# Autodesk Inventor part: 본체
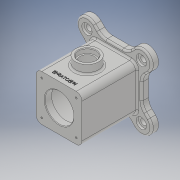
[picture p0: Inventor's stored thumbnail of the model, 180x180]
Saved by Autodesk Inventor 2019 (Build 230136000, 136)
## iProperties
Created: 2021-01
Part Number: 본체
Material: 일반
Document SubType Name: Modeling
Designer: 3dpro14
Density: 1 g/cm^3
Appearance: 기본값
Mass: 385.865 g
Surface Area: 854.376 cm^2
Volume: 385.865 cm^3
Author: 3dpro14
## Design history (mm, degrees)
sketch "스케치1" dims "d26" = 134
  geometry: L1 (22.544, -48)-(-22.544, -48); L2 (-48, -22.544)-(-48, 22.544); L3 (-22.544, 48)-(22.544, 48); L4 (48, 22.544)-(48, -22.544); L5 (60.104, -34.648)-(48, -22.544); L6 (34.648, -60.104)-(22.544, -48); L7 (-34.648, -60.104)-(-22.544, -48); L8 (-60.104, -34.648)-(-48, -22.544); L9 (-60.104, 34.648)-(-48, 22.544); L10 (-34.648, 60.104)-(-22.544, 48); L11 (34.648, 60.104)-(22.544, 48); L12 (60.104, 34.648)-(48, 22.544); L13 (-115.707, 0)-(118.741, 0); L14 (97.225, -97.225)-(-79.645, 79.645); L15 (0, -95.249)-(0, 88.026); L16 (95.516, 0)-(-98.205, 0); L17 (-70.337, -70.337)-(68.388, 68.388); A1 r 18 centre (47.376, -47.376) between (33.054, -58.279) and (58.279, -33.054); A2 r 18 centre (-47.376, -47.376) between (-58.279, -33.054) and (-33.054, -58.279); A3 r 18 centre (-47.376, 47.376) between (-33.054, 58.279) and (-58.279, 33.054); A4 r 18 centre (47.376, 47.376) between (58.279, 33.054) and (33.054, 58.279); 2 further points
  constraints: 34 end point, 16 point on circle, 8 tangent, 7 equal length, 7 point on line, 6 parallel, 4 centre point, 4 perpendicular, 2 horizontal, 1 coincident, 1 vertical, 14 other
  dimensions: "d0" = 96 distance between parallel lines of L3 L1; "d1" = 96 distance between parallel lines of L4 L2; "d2" = 48 distance from line of point (0, 0) L4 (= 0.5 x d1); "d3" = 48 distance from line of point (0, 0) L1 (= 0.5 x d0); "d27" = 36 distance between parallel lines of L6 L5; "d28" = 45 deg angle of L14 L16; "d29" = 45 deg angle of L17 L15; "d30" = 45 deg angle of L13 L14
extrude "돌출1" new body sketch "스케치1" distance "d5" = 12; taper "d6" = 0 deg
fillet "모깎기1" dims "d7" = 20
sketch "스케치2"
  geometry: L1 (40, -40)-(-40, -40); L2 (-40, -40)-(-40, 40); L3 (-40, 40)-(40, 40); L4 (40, 40)-(40, -40); L5 (40, -40)-(-40, 40); L6 (-40, -40)-(40, 40); 1 further point
  constraints: 12 end point, 2 midpoint, 2 parallel, 1 horizontal, 1 perpendicular
  dimensions: "d8" = 80 distance of L1.end L2.end; "d9" = 80 distance of L1.start L1.end
extrude "돌출2" join sketch "스케치2" distance "d10" = 96; taper "d11" = 0 deg
sketch "스케치3"
  geometry: C1 r 25 at (0, 0); 1 further point
  constraints: 1 centre point, 1 coincident
  dimensions: "d12" = 50 diameter of C1
extrude "돌출3" cut sketch "스케치3" distance "d13" = 12; taper "d14" = 0 deg
sketch "스케치4"
  geometry: C1 r 35 at (0, 0); 1 further point
  constraints: 1 centre point, 1 coincident
  dimensions: "d15" = 70 diameter of C1
extrude "돌출4" cut sketch "스케치4" distance "d16" = 84; taper "d17" = 0 deg
sketch "스케치5"
  geometry: C1 r 25 at (0, 0) reference; 1 further point
extrude "돌출5" cut sketch "스케치5" extent not by distance; stored distance "d18" = 84; taper "d19" = 0 deg
fillet "모깎기2" dims "d20" = 3
chamfer "모따기1" distance "d21" = 1; stored, may be unused: second distance "d22" = 2, angle "d23" = 45 deg
sketch "스케치6"
  geometry: L1 (54.26, 0)-(25.74, 0) reference; L2 (54.26, -12)-(25.74, -12) reference; C1 r 20 at (40, 47); 2 further points
  constraints: 1 centre point, 1 midpoint, 1 vertical alignment
  dimensions: "d24" = 59 distance from line of C1.centre L2; "d25" = 40 diameter of C1
extrude "돌출6" join sketch "스케치6" distance "d31" = 15; taper "d32" = 0 deg
sketch "스케치7"
  geometry: C1 r 20 at (0, 0) reference; 2 further points
  constraints: 1 coincident
hole "구멍1" sketch "스케치7" at (0, 0) diameter "d33" = 25; stored, may be unused: countersink angle "d37" = 90 deg, drill point angle "d39" = 0 deg; dims "d34" = 6, "d35" = 30, "d36" = 8, "d38" = 8
sketch "스케치8"
  geometry: L1 (54.26, 0)-(25.74, 0) reference; L2 (0, 96)-(80, 96) reference; 3 further points
  constraints: 1 midpoint, 1 vertical alignment, 1 other
  dimensions: "d40" = 10 distance from line of point (40, 86) L2
feature "엠보싱1" sketch "스케치8" dims "d0" = 96, "d1" = 96, "d2" = 48 (= 0.5 x d1), "d3" = 48 (= 0.5 x d0), "d8" = 80, "d9" = 80, "d26" = 134, "d27" = 36, "d28" = 45 deg, "d29" = 45 deg, "d30" = 45 deg, "d41" = 0.5, "d42" = 0
sketch "스케치9"
  geometry: L1 (-40, 40)-(-40, -40) reference; L2 (40, 40)-(-40, 40) reference; 2 further points
  dimensions: "d43" = 10 distance from line of L1 point (-30, 30); "d44" = 10 distance from line of L2 point (-30, 30)
hole "구멍2" sketch "스케치9" at (-30, 30) diameter "d45" = 3.242; stored, may be unused: countersink angle "d49" = 90 deg, drill point angle "d51" = 118 deg; dims "d46" = 8, "d47" = 4, "d48" = 2, "d50" = 10
sketch "스케치10" dims "d58" = 134
  geometry: L1 (0, 107.205)-(0, -112.361); L2 (-96.353, 96.353)-(89.916, -89.916); 3 further points
  constraints: 4 end point, 3 point on line, 1 coincident, 1 vertical, 3 other
  dimensions: "d59" = 45 deg angle of L2 L1
hole "구멍3" sketch "스케치10" at (-47.376, 47.376) diameter "d60" = 10; stored, may be unused: countersink angle "d64" = 90 deg, drill point angle "d66" = 118 deg; dims "d61" = 8, "d62" = 18, "d63" = 4, "d65" = 10
fillet "모깎기3" dims "d70" = 10
sketch "스케치11"
  geometry: C1 r 1.621 at (30, 30) reference; 2 further points
  constraints: 1 coincident
hole "구멍4" sketch "스케치11" at (30, 30) diameter "d71" = 3.242; stored, may be unused: countersink angle "d75" = 90 deg, drill point angle "d77" = 118 deg; dims "d72" = 8, "d73" = 4, "d74" = 2, "d76" = 10
fillet "모깎기4" dims "d84" = 3
fillet "모깎기5" dims "d85" = 3
chamfer "모따기2" distance "d86" = 1; stored, may be unused: second distance "d87" = 2, angle "d88" = 45 deg
node "솔리드1"
pattern_linear "직사각형 패턴1" dims "d54" = 60, "d57" = 60
pattern_circular "원형 패턴1" dims angle "d68" = 360 deg
pattern_linear "직사각형 패턴2" dims "d80" = 60, "d83" = 60
